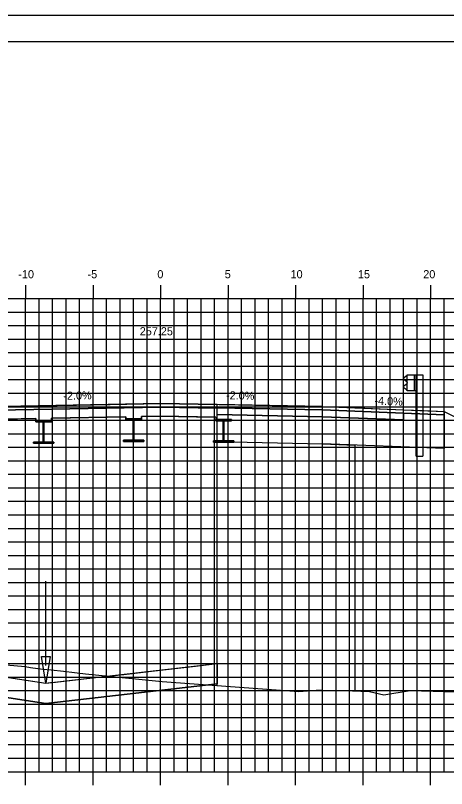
# Model space of a CAD drawing. Extents: x -22 to 1480, y -1511 to 8.
# Drawn here: x 493.7 to 525.6, y -131.7 to -74.5 of the extents above; entities that cross this region are included whole.
import ezdxf

# ---------------------------------------------------------------- set-up
doc = ezdxf.new("R2010")
doc.units = 0
for name, color, linetype in [('ANNOTATION', 7, 'Continuous'), ('BORDER', 7, 'Continuous'), ('D_Bridge_Superstructure', 7, 'Continuous'), ('D_Bridge_Superstructure_Slab', 7, 'Continuous'), ('D_Bridge_Wingwall', 7, 'Continuous'), ('D_Drainage_Ditch_Line', 7, 'Continuous'), ('D_Guardrail_Beam_Lt', 7, 'Continuous'), ('D_Roadway_Centerline', 7, 'Continuous'), ('D_Roadway_Centerline_Text', 7, 'Continuous'), ('D_Roadway_Edge_Shoulder', 7, 'Continuous'), ('D_Roadway_Edge_TW', 7, 'Continuous'), ('D_Roadway_Pavement', 7, 'Continuous'), ('D_Roadway_SlopeLines', 7, 'Continuous'), ('D_Roadway_SubGrade', 7, 'Continuous'), ('H_V ANNOTATION', 7, 'Continuous'), ('MAJOR', 7, 'Continuous'), ('MINOR', 7, 'Continuous'), ('PLOT BOUNDARY', 7, 'Continuous'), ('S_Roadway_Centerline', 7, 'Continuous')]:
    doc.layers.add(name, color=color, linetype=linetype)

msp = doc.modelspace()

# ---------------------------------------------------------------- linework, layer by layer
at = {"layer": 'BORDER'}
msp.add_line((589.452, -76.466), (429.452, -76.466), dxfattribs=at)
at = {"layer": 'D_Bridge_Superstructure'}
for p, q in [((496.369, -104.497), (495.202, -104.497)), ((495.202, -104.497), (495.202, -104.58)), ((495.807, -104.58), (495.765, -104.58)), ((495.807, -104.58), (495.765, -104.58)), ((495.807, -104.58), (496.369, -104.58)), ((496.369, -104.58), (496.369, -104.497)), ((503.036, -104.363), (501.869, -104.363)), ((501.869, -104.363), (501.869, -104.447)), ((502.473, -104.447), (502.432, -104.447)), ((502.473, -104.447), (502.432, -104.447)), ((502.473, -104.447), (503.036, -104.447)), ((503.036, -104.447), (503.036, -104.363)), ((509.702, -104.417), (508.536, -104.417)), ((508.536, -104.417), (508.536, -104.5)), ((509.14, -104.5), (509.098, -104.5)), ((509.14, -104.5), (509.098, -104.5)), ((509.14, -104.5), (509.702, -104.5)), ((509.702, -104.5), (509.702, -104.417)), ((495.765, -106.08), (495.036, -106.08)), ((495.036, -106.08), (495.036, -106.163)), ((495.765, -106.08), (495.036, -106.08)), ((495.807, -106.08), (495.765, -106.08)), ((495.807, -106.08), (495.765, -106.08)), ((502.432, -105.947), (501.702, -105.947)), ((501.702, -105.947), (501.702, -106.03)), ((502.432, -105.947), (501.702, -105.947)), ((502.473, -105.947), (502.432, -105.947)), ((502.473, -105.947), (502.432, -105.947)), ((509.098, -106), (508.369, -106)), ((508.369, -106), (508.369, -106.083)), ((509.098, -106), (508.369, -106)), ((509.14, -106), (509.098, -106)), ((509.14, -106), (509.098, -106))]:
    msp.add_line(p, q, dxfattribs=at)
for points in [[(495.202, -104.497), (496.369, -104.497), (496.369, -104.58), (495.202, -104.58)], [(495.765, -104.58), (495.807, -104.58), (495.807, -106.08), (495.765, -106.08)], [(501.869, -104.363), (503.036, -104.363), (503.036, -104.447), (501.869, -104.447)], [(502.432, -104.447), (502.473, -104.447), (502.473, -105.947), (502.432, -105.947)], [(508.536, -104.417), (509.702, -104.417), (509.702, -104.5), (508.536, -104.5)], [(509.098, -104.5), (509.14, -104.5), (509.14, -106), (509.098, -106)], [(495.036, -106.08), (496.536, -106.08), (496.536, -106.163), (495.036, -106.163)], [(501.702, -105.947), (503.202, -105.947), (503.202, -106.03), (501.702, -106.03)], [(508.369, -106), (509.869, -106), (509.869, -106.083), (508.369, -106.083)]]:
    msp.add_lwpolyline(points, close=True, dxfattribs=at)
for points in [[(495.807, -104.58), (496.369, -104.58), (496.369, -104.497), (495.202, -104.497), (495.202, -104.58), (495.765, -104.58), (495.807, -104.58)], [(495.202, -104.58), (495.765, -104.58), (495.807, -104.58)], [(495.765, -104.58), (495.765, -106.08), (495.807, -106.08), (495.807, -104.58)], [(495.765, -104.58), (495.765, -106.08), (495.807, -106.08), (495.807, -104.58)], [(502.473, -104.447), (503.036, -104.447), (503.036, -104.363), (501.869, -104.363), (501.869, -104.447), (502.432, -104.447), (502.473, -104.447)], [(501.869, -104.447), (502.432, -104.447), (502.473, -104.447)], [(502.432, -104.447), (502.432, -105.947), (502.473, -105.947), (502.473, -104.447)], [(502.432, -104.447), (502.432, -105.947), (502.473, -105.947), (502.473, -104.447)], [(509.14, -104.5), (509.702, -104.5), (509.702, -104.417), (508.536, -104.417), (508.536, -104.5), (509.098, -104.5), (509.14, -104.5)], [(508.536, -104.5), (509.098, -104.5), (509.14, -104.5)], [(509.098, -104.5), (509.098, -106), (509.14, -106), (509.14, -104.5)], [(509.098, -104.5), (509.098, -106), (509.14, -106), (509.14, -104.5)], [(495.036, -106.08), (495.036, -106.163), (496.536, -106.163), (496.536, -106.08), (495.807, -106.08)], [(495.036, -106.163), (496.536, -106.163), (496.536, -106.08), (495.807, -106.08)], [(501.702, -105.947), (501.702, -106.03), (503.202, -106.03), (503.202, -105.947), (502.473, -105.947)], [(501.702, -106.03), (503.202, -106.03), (503.202, -105.947), (502.473, -105.947)], [(508.369, -106), (508.369, -106.083), (509.869, -106.083), (509.869, -106), (509.14, -106)], [(508.369, -106.083), (509.869, -106.083), (509.869, -106), (509.14, -106)]]:
    msp.add_lwpolyline(points, dxfattribs=at)
at = {"layer": 'D_Bridge_Superstructure_Slab'}
for p, q in [((504.452, -103.49), (482.452, -103.93)), ((482.452, -103.93), (504.452, -103.49)), ((508.64, -103.574), (504.452, -103.49)), ((504.452, -103.49), (508.64, -103.574)), ((508.64, -106.053), (508.64, -103.303)), ((508.64, -103.574), (508.64, -103.303)), ((508.64, -104.417), (508.64, -103.574)), ((495.202, -104.342), (495.202, -104.497)), ((501.869, -104.208), (501.869, -104.363)), ((501.869, -104.363), (503.036, -104.363)), ((503.036, -104.185), (504.452, -104.157)), ((503.036, -104.363), (503.036, -104.185)), ((504.452, -104.157), (504.452, -104.157)), ((508.536, -104.238), (508.536, -104.417)), ((508.536, -104.417), (508.64, -104.417))]:
    msp.add_line(p, q, dxfattribs=at)
for points in [[(508.64, -103.574), (504.452, -103.49), (481.286, -103.953)], [(508.64, -103.574), (504.452, -103.49), (481.286, -103.953)], [(508.64, -103.574), (504.452, -103.49), (482.452, -103.93), (482.43, -103.66), (504.452, -103.219), (508.64, -103.303)], [(508.64, -103.303), (504.452, -103.219), (482.43, -103.66), (482.452, -103.93)], [(495.202, -104.342), (489.702, -104.452)], [(489.786, -104.45), (491.119, -104.423), (495.202, -104.342)], [(491.119, -104.423), (495.202, -104.342), (495.202, -104.497), (496.369, -104.497), (496.369, -104.318), (497.786, -104.29), (499.119, -104.263), (501.869, -104.208), (501.869, -104.363), (503.036, -104.363), (503.036, -104.185), (504.452, -104.157), (505.786, -104.183), (507.119, -104.21), (508.536, -104.238), (508.536, -104.417), (508.64, -104.417)], [(496.369, -104.318), (496.369, -104.497), (495.202, -104.497), (495.202, -104.342)], [(495.202, -104.497), (496.369, -104.497), (496.369, -104.318)], [(501.869, -104.208), (496.369, -104.318)], [(496.369, -104.318), (497.786, -104.29), (499.119, -104.263), (501.869, -104.208)], [(503.036, -104.185), (503.036, -104.363), (501.869, -104.363), (501.869, -104.208)], [(508.536, -104.238), (504.452, -104.157), (503.036, -104.185)], [(504.452, -104.157), (505.786, -104.183), (507.119, -104.21), (508.536, -104.238)], [(508.536, -104.238), (508.536, -104.417), (508.64, -104.417)]]:
    msp.add_lwpolyline(points, dxfattribs=at)
at = {"layer": 'D_Bridge_Wingwall'}
msp.add_lwpolyline([(508.64, -124.093), (508.64, -106.053), (516.452, -106.209), (518.831, -106.304), (518.831, -124.492)], dxfattribs=at)
at = {"layer": 'D_Drainage_Ditch_Line'}
msp.add_line((495.95, -122.606), (495.95, -116.363), dxfattribs=at)
msp.add_lwpolyline([(495.622, -121.95), (496.278, -121.95), (495.95, -123.918)], close=True, dxfattribs=at)
at = {"layer": 'D_Guardrail_Beam_Lt'}
for p, q in [((522.633, -101.22), (522.49, -101.32)), ((522.723, -101.199), (522.649, -101.214)), ((522.723, -101.116), (523.411, -101.116)), ((522.723, -102.282), (522.723, -101.116)), ((523.244, -101.116), (523.244, -102.282)), ((523.348, -101.116), (523.348, -102.282)), ((523.411, -101.116), (523.881, -101.116)), ((523.411, -101.116), (523.411, -102.282)), ((523.881, -101.116), (523.881, -107.116)), ((522.49, -101.463), (522.685, -101.6)), ((522.719, -101.664), (522.719, -101.734)), ((522.685, -101.799), (522.49, -101.935)), ((522.49, -102.078), (522.633, -102.178)), ((522.649, -102.185), (522.723, -102.199)), ((523.411, -102.282), (522.723, -102.282)), ((523.39, -107.116), (523.39, -102.282)), ((523.39, -107.116), (523.881, -107.116))]:
    msp.add_line(p, q, dxfattribs=at)
for centre, major_axis, start_param, end_param in [((522.657, -101.254), (-0.0417, 0), 4.907132, 5.323254), ((522.54, -101.392), (-0.0877, 0), 5.323254, 7.243116), ((522.64, -101.664), (0.0789, 0), 0, 0.959931), ((522.64, -101.734), (0.0789, 0), 5.323254, 6.283185), ((522.54, -102.006), (-0.0877, 0), 5.323254, 7.243116), ((522.657, -102.144), (-0.0417, 0), 0.959931, 1.376053)]:
    msp.add_ellipse(centre, major_axis=major_axis, ratio=0.995501, start_param=start_param, end_param=end_param, dxfattribs=at)
at = {"layer": 'D_Roadway_Centerline'}
for points in [[(482.43, -103.66), (484.452, -103.619), (485.173, -103.605), (487.585, -103.556), (492.452, -103.459), (498.212, -103.344), (504.452, -103.219), (510.212, -103.334), (516.452, -103.459), (519.572, -103.584), (522.452, -103.699), (523.952, -103.759), (525.452, -103.819)], [(464.735, -120.758), (464.762, -120.759), (464.937, -120.767), (468.724, -120.944), (470.022, -121.008), (472.661, -121.133), (475.308, -121.266), (476.598, -121.328), (480.36, -121.519), (480.534, -121.546), (480.594, -121.555), (484.471, -122.162), (485.881, -122.382), (488.408, -122.778), (491.167, -123.209), (492.356, -123.386), (495.95, -123.918), (496.306, -123.878), (496.453, -123.862), (500.05, -123.457), (501.74, -123.267), (503.787, -123.034), (507.026, -122.664), (508.64, -122.47)]]:
    msp.add_lwpolyline(points, dxfattribs=at)
at = {"layer": 'D_Roadway_Edge_Shoulder'}
msp.add_lwpolyline([(516.452, -103.459), (522.452, -103.699), (522.452, -103.699), (525.452, -103.819), (525.452, -104.069), (522.452, -103.949), (522.452, -103.949), (516.452, -103.709)], close=True, dxfattribs=at)
at = {"layer": 'D_Roadway_Edge_TW'}
msp.add_lwpolyline([(508.64, -103.553), (516.452, -103.709), (516.452, -103.459), (508.64, -103.303)], dxfattribs=at)
at = {"layer": 'D_Roadway_Pavement'}
for points in [[(508.64, -104.053), (516.452, -104.209), (516.452, -103.709), (508.64, -103.553)], [(516.452, -103.709), (522.452, -103.949), (522.452, -103.949), (522.452, -104.449), (516.452, -104.209), (516.452, -103.709)]]:
    msp.add_lwpolyline(points, dxfattribs=at)
at = {"layer": 'D_Roadway_SlopeLines'}
msp.add_line((525.452, -103.819), (529.366, -105.776), dxfattribs=at)
for points in [[(480.36, -121.519), (495.95, -123.918)], [(480.36, -121.519), (480.36, -123.019), (495.95, -125.418), (508.64, -123.97)], [(495.95, -123.918), (508.64, -122.47)]]:
    msp.add_lwpolyline(points, dxfattribs=at)
msp.add_lwpolyline([(480.36, -121.519), (495.95, -123.918), (508.64, -122.47), (508.64, -123.97), (495.95, -125.418), (480.36, -123.019)], close=True, dxfattribs=at)
at = {"layer": 'D_Roadway_SubGrade'}
msp.add_lwpolyline([(508.64, -106.053), (516.452, -106.209), (516.452, -104.209), (508.64, -104.053)], dxfattribs=at)
msp.add_lwpolyline([(516.452, -104.209), (522.452, -104.449), (522.452, -103.949), (525.452, -104.069), (525.452, -103.819), (525.452, -106.569), (516.452, -106.209)], close=True, dxfattribs=at)
at = {"layer": 'MAJOR'}
for p, q in [((494.452, -94.464), (494.452, -95.466)), ((499.452, -94.464), (499.452, -95.466)), ((504.452, -94.464), (504.452, -95.466)), ((509.452, -94.464), (509.452, -95.466)), ((514.452, -94.464), (514.452, -95.466)), ((519.452, -94.464), (519.452, -95.466)), ((524.452, -94.464), (524.452, -95.466)), ((434.452, -95.466), (574.452, -95.466)), ((434.452, -95.466), (574.452, -95.466)), ((494.452, -130.466), (494.452, -95.466)), ((499.452, -130.466), (499.452, -95.466)), ((504.452, -130.466), (504.452, -95.466)), ((509.452, -130.466), (509.452, -95.466)), ((514.452, -130.466), (514.452, -95.466)), ((519.452, -130.466), (519.452, -95.466)), ((524.452, -130.466), (524.452, -95.466)), ((434.452, -100.466), (574.452, -100.466)), ((434.452, -105.466), (574.452, -105.466)), ((434.452, -110.466), (574.452, -110.466)), ((434.452, -115.466), (574.452, -115.466)), ((434.452, -120.466), (574.452, -120.466)), ((434.452, -125.466), (574.452, -125.466)), ((434.452, -130.466), (574.452, -130.466)), ((434.452, -130.466), (574.452, -130.466)), ((494.452, -131.468), (494.452, -130.466)), ((499.452, -131.468), (499.452, -130.466)), ((504.452, -131.468), (504.452, -130.466)), ((509.452, -131.468), (509.452, -130.466)), ((514.452, -131.468), (514.452, -130.466)), ((519.452, -131.468), (519.452, -130.466)), ((524.452, -131.468), (524.452, -130.466))]:
    msp.add_line(p, q, dxfattribs=at)
at = {"layer": 'MINOR'}
for p, q in [((495.452, -130.466), (495.452, -95.466)), ((496.452, -130.466), (496.452, -95.466)), ((497.452, -130.466), (497.452, -95.466)), ((498.452, -130.466), (498.452, -95.466)), ((500.452, -130.466), (500.452, -95.466)), ((501.452, -130.466), (501.452, -95.466)), ((502.452, -130.466), (502.452, -95.466)), ((503.452, -130.466), (503.452, -95.466)), ((505.452, -130.466), (505.452, -95.466)), ((506.452, -130.466), (506.452, -95.466)), ((507.452, -130.466), (507.452, -95.466)), ((508.452, -130.466), (508.452, -95.466)), ((510.452, -130.466), (510.452, -95.466)), ((511.452, -130.466), (511.452, -95.466)), ((512.452, -130.466), (512.452, -95.466)), ((513.452, -130.466), (513.452, -95.466)), ((515.452, -130.466), (515.452, -95.466)), ((516.452, -130.466), (516.452, -95.466)), ((517.452, -130.466), (517.452, -95.466)), ((518.452, -130.466), (518.452, -95.466)), ((520.452, -130.466), (520.452, -95.466)), ((521.452, -130.466), (521.452, -95.466)), ((522.452, -130.466), (522.452, -95.466)), ((523.452, -130.466), (523.452, -95.466)), ((525.452, -130.466), (525.452, -95.466)), ((434.452, -96.466), (574.452, -96.466)), ((434.452, -97.466), (574.452, -97.466)), ((434.452, -98.466), (574.452, -98.466)), ((434.452, -99.466), (574.452, -99.466)), ((434.452, -101.466), (574.452, -101.466)), ((434.452, -102.466), (574.452, -102.466)), ((434.452, -103.466), (574.452, -103.466)), ((434.452, -104.466), (574.452, -104.466)), ((434.452, -106.466), (574.452, -106.466)), ((434.452, -107.466), (574.452, -107.466)), ((434.452, -108.466), (574.452, -108.466)), ((434.452, -109.466), (574.452, -109.466)), ((434.452, -111.466), (574.452, -111.466)), ((434.452, -112.466), (574.452, -112.466)), ((434.452, -113.466), (574.452, -113.466)), ((434.452, -114.466), (574.452, -114.466)), ((434.452, -116.466), (574.452, -116.466)), ((434.452, -117.466), (574.452, -117.466)), ((434.452, -118.466), (574.452, -118.466)), ((434.452, -119.466), (574.452, -119.466)), ((434.452, -121.466), (574.452, -121.466)), ((434.452, -122.466), (574.452, -122.466)), ((434.452, -123.466), (574.452, -123.466)), ((434.452, -124.466), (574.452, -124.466)), ((434.452, -126.466), (574.452, -126.466)), ((434.452, -127.466), (574.452, -127.466)), ((434.452, -128.466), (574.452, -128.466)), ((434.452, -129.466), (574.452, -129.466))]:
    msp.add_line(p, q, dxfattribs=at)
at = {"layer": 'PLOT BOUNDARY'}
msp.add_lwpolyline([(421.359, -184.525), (591.359, -184.525), (591.359, -74.525), (421.359, -74.525)], close=True, dxfattribs=at)
at = {"layer": 'S_Roadway_Centerline'}
msp.add_lwpolyline([(491.297, -122.404), (494.415, -122.684), (494.807, -122.75), (495.723, -122.888), (496.352, -122.925), (497.268, -123.018), (498.889, -123.227), (504.579, -123.8), (514.692, -124.53), (515.984, -124.431), (516.372, -124.43), (518.035, -124.472), (519.917, -124.546), (520.985, -124.774), (522.931, -124.455), (526.306, -124.548)], dxfattribs=at)

# ---------------------------------------------------------------- texts
at = {"layer": 'ANNOTATION'}
for s, rotation, p in [('-2.0%', 1.1458, (497.255, -102.963)), ('-2.0%', 358.8542, (509.295, -102.916)), ('-4.0%', 357.7094, (520.28, -103.314))]:
    msp.add_text(s, height=0.6, rotation=rotation, dxfattribs=at).set_placement(p)
at = {"layer": 'D_Roadway_Centerline'}
for s, p in [('C', (504.447, -103.219)), ('L', (504.452, -103.226))]:
    msp.add_text(s, height=0.0146, dxfattribs=at).set_placement(p)
at = {"layer": 'D_Roadway_Centerline_Text'}
msp.add_text('257.25', height=0.6, dxfattribs=at).set_placement((502.908, -98.187))
at = {"layer": 'H_V ANNOTATION'}
for s, p in [('-10', (493.917, -93.966)), ('-5', (499.043, -93.966)), ('0', (504.211, -93.966)), ('5', (509.203, -93.966)), ('10', (514.078, -93.966)), ('15', (519.07, -93.966)), ('20', (523.906, -93.966))]:
    msp.add_text(s, height=0.6, dxfattribs=at).set_placement(p)

doc.saveas('drawing.dxf')
